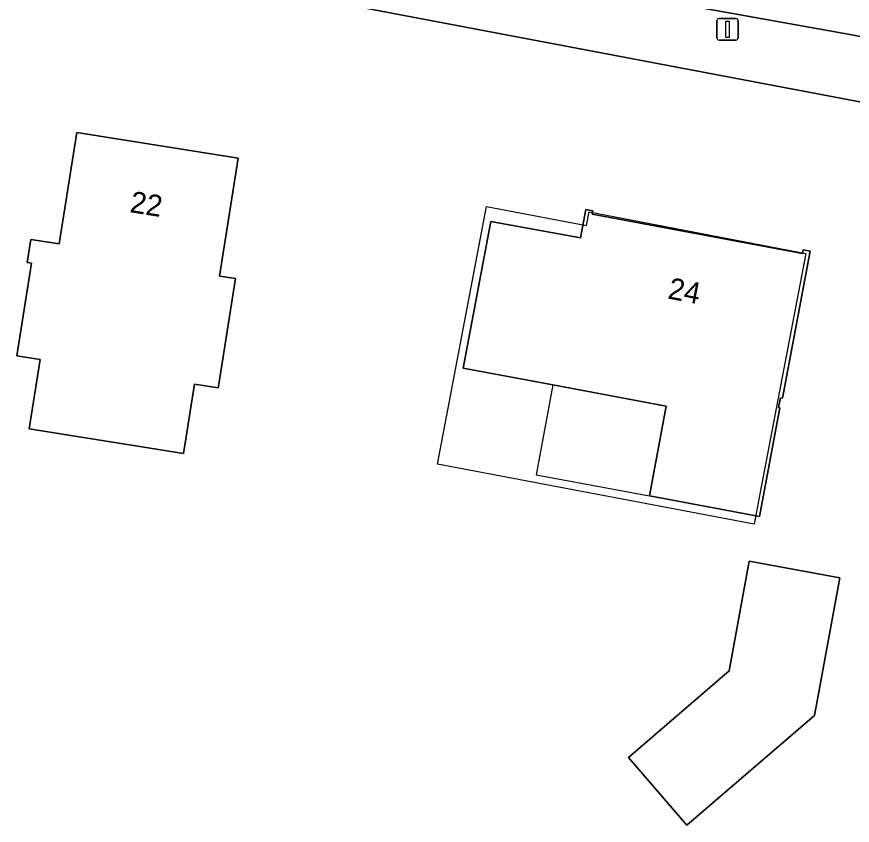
# Model space of a CAD drawing. Extents: x 161258 to 161838, y 380833 to 381727.
# Drawn here: x 161658.55 to 161697.58, y 381115.37 to 381153.12 of the extents above; entities that cross this region are included whole.
import ezdxf

# ---------------------------------------------------------------- set-up
doc = ezdxf.new("R2010")
doc.units = 0
for name, color, linetype in [('IMGEO_Erf', 7, 'Continuous'), ('IMGEO_Lichtmast', 7, 'Continuous'), ('IMGEO_Pand', 7, 'Continuous'), ('IMGEO_Pand_nummerreeks', 7, 'Continuous'), ('IMGEO_Pand_overbouw', 7, 'Continuous'), ('IMGEO_Pand_vergunning_verleend', 7, 'Continuous'), ('IMGEO_Rijbaan_lokaal_open', 7, 'Continuous'), ('IMGEO_Voetpad_open', 7, 'Continuous')]:
    doc.layers.add(name, color=color, linetype=linetype)

msp = doc.modelspace()

# ---------------------------------------------------------------- linework, layer by layer
at = {"layer": 'IMGEO_Erf'}
msp.add_lwpolyline([(161729.059, 381143.246), (161705.296, 381147.752), (161698.258, 381149.087), (161668.75, 381154.683)], dxfattribs=at)
for points in [[(161659.236, 381141.61), (161659.038, 381141.641), (161659.21, 381142.727), (161660.533, 381142.516), (161661.358, 381147.71), (161668.9, 381146.511), (161668.026, 381141.014), (161668.776, 381140.895), (161667.991, 381135.958), (161667.964, 381135.79), (161666.858, 381135.966), (161666.344, 381132.729), (161659.13, 381133.874), (161659.644, 381137.111), (161658.549, 381137.285)], [(161688.892, 381134.939), (161683.6, 381135.93), (161679.41, 381136.715), (161680.699, 381143.566), (161684.887, 381142.795), (161685.137, 381144.124), (161685.456, 381144.064), (161685.427, 381143.903), (161695.256, 381142.074), (161695.288, 381142.238), (161695.61, 381142.176), (161694.322, 381135.306), (161694.224, 381135.324), (161694.139, 381134.872), (161694.198, 381134.861), (161693.246, 381129.779), (161688.106, 381130.743)], [(161692.767, 381127.7), (161697.007, 381126.922), (161695.812, 381120.499), (161689.848, 381115.366), (161687.122, 381118.535), (161691.829, 381122.585)]]:
    msp.add_lwpolyline(points, close=True, dxfattribs=at)
at = {"layer": 'IMGEO_Lichtmast'}
for p, q in [((161691.359, 381153.034), (161692.149, 381153.034)), ((161692.149, 381153.034), (161691.359, 381153.034)), ((161691.259, 381152.134), (161691.259, 381152.934)), ((161691.259, 381152.934), (161691.259, 381152.134)), ((161692.249, 381152.934), (161692.249, 381152.134)), ((161692.249, 381152.134), (161692.249, 381152.934)), ((161692.149, 381152.034), (161691.359, 381152.034)), ((161691.359, 381152.034), (161692.149, 381152.034))]:
    msp.add_line(p, q, dxfattribs=at)
msp.add_lwpolyline([(161691.679, 381152.909), (161691.829, 381152.909), (161691.829, 381152.159), (161691.679, 381152.159), (161691.679, 381152.909)], dxfattribs=at)
for centre, start, end in [((161691.359, 381152.934), 90, 180), ((161691.359, 381152.934), 90, 180), ((161692.149, 381152.934), 0, 90), ((161692.149, 381152.934), 360, 90), ((161691.359, 381152.134), 180, 270), ((161691.359, 381152.134), 180, 270), ((161692.149, 381152.134), 270, 0), ((161692.149, 381152.134), 270, 0)]:
    msp.add_arc(centre, 0.1, start, end, dxfattribs=at)
at = {"layer": 'IMGEO_Pand'}
for points in [[(161668.026, 381141.014), (161668.9, 381146.511), (161661.358, 381147.71), (161660.533, 381142.516), (161659.21, 381142.727), (161659.038, 381141.641), (161659.236, 381141.61), (161658.549, 381137.285), (161659.644, 381137.111), (161659.13, 381133.874), (161666.344, 381132.729), (161666.858, 381135.966), (161667.964, 381135.79), (161667.991, 381135.958), (161668.776, 381140.895)], [(161695.61, 381142.176), (161695.288, 381142.238), (161695.256, 381142.074), (161685.427, 381143.903), (161685.456, 381144.064), (161685.137, 381144.124), (161684.887, 381142.795), (161680.699, 381143.566), (161679.41, 381136.715), (161683.6, 381135.93), (161688.892, 381134.939), (161688.106, 381130.743), (161693.246, 381129.779), (161694.198, 381134.861), (161694.139, 381134.872), (161694.224, 381135.324), (161694.322, 381135.306)], [(161697.007, 381126.922), (161692.767, 381127.7), (161691.829, 381122.585), (161687.122, 381118.535), (161689.848, 381115.366), (161695.812, 381120.499)]]:
    msp.add_lwpolyline(points, close=True, dxfattribs=at)
at = {"layer": 'IMGEO_Pand_overbouw'}
msp.add_lwpolyline([(161688.106, 381130.743), (161688.892, 381134.939), (161683.6, 381135.93), (161682.814, 381131.736)], close=True, dxfattribs=at)
at = {"layer": 'IMGEO_Pand_vergunning_verleend'}
msp.add_lwpolyline([(161678.207, 381132.236), (161680.497, 381144.263), (161685.166, 381143.374), (161685.286, 381144.007), (161695.413, 381142.073), (161693.282, 381130.914), (161692.998, 381129.421)], close=True, dxfattribs=at)
at = {"layer": 'IMGEO_Rijbaan_lokaal_open'}
msp.add_lwpolyline([(161669.154, 381157.523), (161682.076, 381155.063), (161697.566, 381152.273), (161698.283, 381152.136), (161706.149, 381150.632), (161710.948, 381149.714), (161728.168, 381146.455), (161735.396, 381145.088), (161735.76, 381147.064), (161736.147, 381148.935), (161736.521, 381150.931), (161729.309, 381152.304), (161712.607, 381155.438), (161707.169, 381156.459), (161706.789, 381156.53), (161698.673, 381158.104), (161690.593, 381159.591), (161684.811, 381160.667), (161677.82, 381161.927), (161671.905, 381162.945)], dxfattribs=at)
at = {"layer": 'IMGEO_Voetpad_open'}
msp.add_lwpolyline([(161668.75, 381154.683), (161698.258, 381149.087), (161698.283, 381152.136), (161697.566, 381152.273), (161682.076, 381155.063)], dxfattribs=at)

# ---------------------------------------------------------------- texts
at = {"layer": 'IMGEO_Pand_nummerreeks'}
for s, rotation, p in [('22', 350.9645, (161663.795, 381144.001)), ('24', 349.1883, (161688.923, 381139.972))]:
    msp.add_text(s, height=1, rotation=rotation, dxfattribs=at).set_placement(p)

doc.saveas('drawing.dxf')
